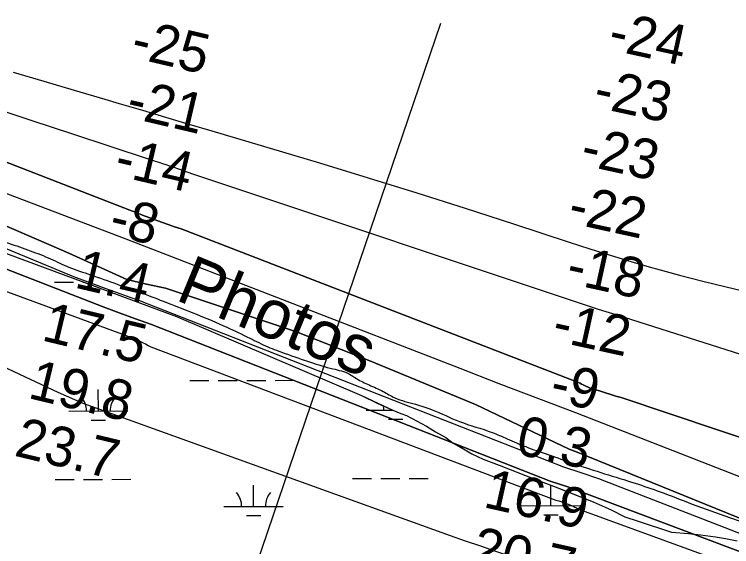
# Model space of a CAD drawing. Extents: x 3361039 to 3398939, y 576572 to 602007.
# Drawn here: x 3392837 to 3394047, y 583836 to 584734 of the extents above; entities that cross this region are included whole.
import ezdxf

# ---------------------------------------------------------------- set-up
doc = ezdxf.new("R2010")
doc.units = 0
for name, color, linetype in [('V-RIVR-EDGE', 7, 'Continuous'), ('V-RIVR-IDEN', 7, 'Continuous'), ('V-RIVR-RANG', 7, 'Continuous'), ('V-SITE-VEGE', 7, 'Continuous'), ('V-TOPO-DPTH', 7, 'Continuous'), ('V-TOPO-MINR', 7, 'Continuous'), ('V-TOPO-WATR', 7, 'Continuous'), ('V-WETL-SWMP', 7, 'Continuous')]:
    doc.layers.add(name, color=color, linetype=linetype)

msp = doc.modelspace()

# ---------------------------------------------------------------- linework, layer by layer
at = {"layer": 'V-RIVR-EDGE'}
msp.add_spline([(3387368.6, 585771), (3387389, 585767.6), (3387407.3, 585766.1), (3387418.2, 585761.7), (3387425.5, 585756.5), (3387441.6, 585752.8), (3387452.6, 585751.4), (3387462.1, 585753.9), (3387477.4, 585758.2), (3387482.9, 585759.3), (3387491.7, 585759.3), (3387502.3, 585758.2), (3387510.3, 585756.3), (3387521.6, 585753), (3387530.1, 585752.3), (3387538.5, 585752.2), (3387549.8, 585752.2), (3387558.9, 585755.5), (3387571.4, 585756.9), (3387583.4, 585757.3), (3387598.4, 585756.1), (3387629.8, 585749.5), (3387659.8, 585743.5), (3387703.3, 585736.8), (3387727.4, 585734.2), (3387739.1, 585733.5), (3387750.8, 585734.2), (3387753.7, 585731.6), (3387763.2, 585723.9), (3387774.5, 585720.6), (3387790.6, 585719.8), (3387800.1, 585721.6), (3387814, 585720.1), (3387824.6, 585720.1), (3387847.3, 585714.2), (3387884.2, 585709.4), (3387930.2, 585702.7), (3387980.6, 585701.1), (3388035.1, 585696.5), (3388076, 585694.6), (3388096.9, 585693.8), (3388120.3, 585690.5), (3388145.1, 585685.3), (3388171.8, 585682.3), (3388198.8, 585676.8), (3388222.6, 585669.4), (3388245.6, 585660.6), (3388260.9, 585655.4), (3388279.6, 585655.4), (3388291.3, 585658.3), (3388298.9, 585663.7), (3388299.3, 585666.3), (3388299, 585670.7), (3388290.6, 585674.4), (3388291.7, 585677.3), (3388293.9, 585678.4), (3388303, 585677.6), (3388318.7, 585676.5), (3388334.1, 585672.8), (3388354.1, 585663.6), (3388357.1, 585659.9), (3388363.3, 585658.1), (3388368.4, 585658.1), (3388371, 585661), (3388375.3, 585662.1), (3388379, 585661.3), (3388383, 585659.1), (3388383.7, 585654.4), (3388384.1, 585649.3), (3388389.9, 585647.4), (3388406, 585642.3), (3388468.9, 585637.7), (3388491.5, 585635.8), (3388534.6, 585628.4), (3388578.1, 585619.2), (3388610.6, 585613.6), (3388635.9, 585612.1), (3388727.9, 585599.4), (3388768.5, 585591.7), (3388822.6, 585580.9), (3388865, 585570.6), (3388906.6, 585562.8), (3388924.1, 585559.5), (3388938.8, 585562), (3388961.4, 585563.4), (3388974.2, 585560.1), (3389007.5, 585553.4), (3389018.8, 585554.5), (3389027.2, 585555.9), (3389037.1, 585555.9), (3389051.7, 585553.7), (3389061.2, 585553.3), (3389081.3, 585552.1), (3389098.1, 585551), (3389120.4, 585548.7), (3389143.4, 585546.5), (3389160.2, 585542.1), (3389200.8, 585534.7), (3389222.3, 585525.1), (3389247.2, 585519.2), (3389280.4, 585509.6), (3389307.5, 585497.8), (3389334.5, 585487.2), (3389349.5, 585483.1), (3389361.5, 585483.1), (3389382.7, 585479), (3389397, 585476.8), (3389416.7, 585468.7), (3389441.9, 585458.4), (3389464.9, 585451.4), (3389479.5, 585449.2), (3389506.2, 585446.2), (3389533.2, 585447.2), (3389558.5, 585444.2), (3389577.8, 585437.9), (3389603.4, 585431.3), (3389618.7, 585425.1), (3389639.2, 585415.1), (3389657.8, 585410.3), (3389693.2, 585404.8), (3389768.9, 585383), (3389806.5, 585373), (3389854.3, 585362.3), (3389881.7, 585358.6), (3389913.9, 585354.5), (3389953.7, 585349.3), (3390008.2, 585341.8), (3390037.8, 585336.3), (3390074.3, 585327.8), (3390128, 585312.7), (3390164.5, 585301.6), (3390200.7, 585289.8), (3390292.7, 585255.6), (3390327.1, 585241.3), (3390360.7, 585231.7), (3390404.5, 585221), (3390454.9, 585214.3), (3390483.1, 585210.5), (3390491.8, 585209.4), (3390494.4, 585207.2), (3390501.3, 585201), (3390507.9, 585200.6), (3390527.3, 585196.2), (3390545.9, 585195), (3390557.6, 585194.3), (3390574.4, 585189.8), (3390605.5, 585179.5), (3390698.6, 585148.2), (3390763.2, 585126.9), (3390811.1, 585111), (3390852.4, 585097.8), (3390900.9, 585081.6), (3390948.1, 585063.5), (3390993.7, 585048.4), (3391036.8, 585031.9), (3391070.8, 585020.1), (3391140.5, 584997.6), (3391201.5, 584974.1), (3391247.5, 584957.5), (3391310.7, 584933.6), (3391362.2, 584914.8), (3391400.6, 584900.1), (3391441.8, 584885.7), (3391505.4, 584861.1), (3391563.5, 584841.9), (3391658.8, 584807.3), (3391712.8, 584786), (3391758.8, 584767.3), (3391796.1, 584749.6), (3391880.4, 584718.3), (3391926.8, 584701.4), (3391969.2, 584685.2), (3392003.9, 584666.9), (3392040, 584650.3), (3392077.6, 584636), (3392135.7, 584613.2), (3392164.9, 584598.1), (3392196, 584583.8), (3392224.8, 584578.2), (3392263.5, 584567.9), (3392290.6, 584559.8), (3392322.7, 584546.5), (3392396.5, 584512.7), (3392439.9, 584496.2), (3392471.7, 584484.8), (3392502, 584473.3), (3392510.8, 584467.5), (3392535.2, 584458.3), (3392606.1, 584432.9), (3392632.4, 584421.5), (3392666.7, 584406.8), (3392715.6, 584386.9), (3392777.4, 584364.8), (3392827, 584348.3), (3392863.6, 584335.4), (3392897.9, 584321.8), (3392928.6, 584307.8), (3392965.4, 584294.9), (3393010, 584279.1), (3393054.6, 584263.2), (3393092.5, 584248.5), (3393195.2, 584206.6), (3393234.2, 584187.9), (3393264.5, 584173.5), (3393294.1, 584162.1), (3393336.8, 584147.4), (3393374.5, 584136.3), (3393402.2, 584127.5), (3393414.3, 584119.8), (3393435.4, 584109.1), (3393459.2, 584098.1), (3393478.9, 584087.5), (3393513.6, 584076.4), (3393541.7, 584067.2), (3393588.1, 584047.4), (3393643.2, 584028.9), (3393668.4, 584018.3), (3393699.8, 584005), (3393737.1, 583991.8), (3393781.7, 583976), (3393884.7, 583943.2), (3393927, 583928.8), (3393981.1, 583908.2), (3394043.9, 583885.4), (3394095.8, 583868.1), (3394154.9, 583847.1), (3394200.2, 583830.5), (3394247, 583816.2), (3394293, 583801.4), (3394349.6, 583781.2), (3394409.1, 583754.7), (3394451.8, 583730.5), (3394470.5, 583720.2), (3394481.8, 583715.4), (3394494.2, 583713.6), (3394502.6, 583708.1), (3394507.3, 583700.4), (3394511.3, 583697.8), (3394522.7, 583692.3), (3394557.3, 583675.8), (3394600.4, 583659.9), (3394658.1, 583638.9), (3394704.5, 583623.5), (3394760.4, 583607.6), (3394824, 583588.8), (3394867.8, 583570.8), (3394925.9, 583546.9), (3394972.2, 583528.9), (3394995.6, 583520), (3395064.7, 583504.2), (3395088.4, 583499.3), (3395120.2, 583491.6), (3395149.1, 583480.5), (3395173.2, 583476.8), (3395201.3, 583471.3), (3395236.4, 583459.9), (3395256.8, 583451.8), (3395280.9, 583445.5), (3395300.3, 583445.1), (3395316.7, 583440.7), (3395324.4, 583433.3), (3395335.3, 583426), (3395353.6, 583417.9), (3395398.9, 583403.9), (3395426.3, 583397.2), (3395442, 583391), (3395455.9, 583383.3), (3395476, 583377.8), (3395495.7, 583369.3), (3395511, 583368.2), (3395530.4, 583365.9), (3395550.5, 583361.8), (3395654.6, 583334.9), (3395704.7, 583322.4), (3395743.7, 583306.9), (3395765.3, 583295.5), (3395788.3, 583286.3), (3395816.4, 583278.9), (3395861.7, 583270.8), (3395916.2, 583261.5), (3395960.7, 583252.6), (3396008.6, 583242.6), (3396060.8, 583230.5), (3396093.4, 583222.3), (3396135.4, 583208.7), (3396170.1, 583199.8), (3396204.4, 583191.3), (3396254.8, 583177.3), (3396301.2, 583165.9), (3396364.4, 583152.9), (3396399.1, 583144.4), (3396426.9, 583138.5), (3396463.1, 583133), (3396489.8, 583132.9), (3396523.4, 583130.2), (3396607.8, 583114), (3396670.3, 583102.1), (3396708.3, 583095.4), (3396743, 583089.5), (3396775.1, 583083.9)], degree=3, dxfattribs=at)
at = {"layer": 'V-RIVR-RANG'}
msp.add_line((3393169.6, 583583.4), (3393556.8, 584719.2), dxfattribs=at)
at = {"layer": 'V-SITE-VEGE'}
for p, q in [((3392696.5, 584377.7), (3393110.5, 584224.5)), ((3393110.5, 584224.5), (3393422.5, 584091.4)), ((3393422.5, 584091.4), (3393450.5, 584078)), ((3393450.5, 584078), (3393475.6, 584066.4)), ((3393475.6, 584066.4), (3393489.2, 584061.1)), ((3393489.2, 584061.1), (3393498.7, 584057.7)), ((3393498.7, 584057.7), (3393515.7, 584048.8)), ((3393515.7, 584048.8), (3393532.5, 584039.8)), ((3393532.5, 584039.8), (3393547.4, 584030.2)), ((3393547.4, 584030.2), (3393565.3, 584020.2)), ((3393565.3, 584020.2), (3393577.2, 584011.1)), ((3393577.2, 584011.1), (3393609, 583992.8)), ((3393609, 583992.8), (3393627.8, 583983.8)), ((3393627.8, 583983.8), (3393655.2, 583973.6)), ((3393655.2, 583973.6), (3393715.3, 583949.9)), ((3393715.3, 583949.9), (3393746.6, 583938.2)), ((3393746.6, 583938.2), (3393813.9, 583911.9)), ((3393813.9, 583911.9), (3393844, 583898.3)), ((3393844, 583898.3), (3393867, 583886.8)), ((3393867, 583886.8), (3393889.8, 583879)), ((3393889.8, 583879), (3393945.8, 583860.5)), ((3393945.8, 583860.5), (3393974.4, 583858.5)), ((3393974.4, 583858.5), (3393995.1, 583856.4)), ((3393995.1, 583856.4), (3394020, 583852.8)), ((3394020, 583852.8), (3394037.2, 583850)), ((3394037.2, 583850), (3394056.8, 583846.3))]:
    msp.add_line(p, q, dxfattribs=at)
at = {"layer": 'V-TOPO-DPTH'}
for points in [[(3394697.5, 583807.4), (3393861, 584087.8), (3393852.2, 584090.4), (3393843.5, 584093.1), (3393834.8, 584095.7), (3393826.1, 584098.3), (3393816.3, 584101.3), (3393812.5, 584102.5), (3393808.8, 584103.9), (3393805.1, 584105.4), (3393801.5, 584107.1), (3393799.2, 584108.2), (3393796.8, 584109.4), (3393794.3, 584110.6), (3393791.9, 584111.8), (3393118, 584372.5), (3393107.1, 584376), (3393096.1, 584379.7), (3393085.3, 584383.5), (3393074.4, 584387.5), (3393063.7, 584391.6), (3393052.9, 584395.7), (3393042.2, 584399.9), (3393031.5, 584404.1), (3392383, 584655.6)], [(3392383, 584655.6), (3393031.5, 584404.1), (3393042.2, 584399.9), (3393052.9, 584395.7), (3393063.7, 584391.6), (3393074.4, 584387.5), (3393085.3, 584383.5), (3393096.1, 584379.7), (3393107.1, 584376), (3393118, 584372.5), (3393791.9, 584111.8), (3393794.3, 584110.6), (3393796.8, 584109.4), (3393799.2, 584108.2), (3393801.5, 584107.1), (3393805.1, 584105.4), (3393808.8, 584103.9), (3393812.5, 584102.5), (3393816.3, 584101.3), (3393826.1, 584098.3), (3393834.8, 584095.7), (3393843.5, 584093.1), (3393852.2, 584090.4), (3393861, 584087.8), (3394697.5, 583807.4)], [(3392834.9, 584637), (3392886.4, 584621.7), (3392937.8, 584606.5), (3392989.2, 584591.3), (3393013.8, 584584.1), (3393052.9, 584572.5), (3393092.1, 584560.9), (3393131.2, 584549.3), (3393170.3, 584537.7), (3393351.6, 584483.6), (3393433.7, 584458.7), (3393515.8, 584433.4), (3393597.6, 584407.3), (3393679.2, 584380.9), (3393773.4, 584349.9), (3393807.9, 584338.8), (3393842.6, 584327.9), (3393877.3, 584317.5), (3393912.2, 584307.3), (3393920.5, 584305), (3393959.6, 584294.2), (3393998.9, 584283.9), (3394038.4, 584274.4), (3394078, 584265.3)], [(3392834.9, 584637), (3392886.4, 584621.7), (3392937.8, 584606.5), (3392989.2, 584591.3), (3393013.8, 584584.1), (3393052.9, 584572.5), (3393092.1, 584560.9), (3393131.2, 584549.3), (3393170.3, 584537.7), (3393351.6, 584483.6), (3393433.7, 584458.7), (3393515.8, 584433.4), (3393597.6, 584407.3), (3393679.2, 584380.9), (3393773.4, 584349.9), (3393807.9, 584338.8), (3393842.6, 584327.9), (3393877.3, 584317.5), (3393912.2, 584307.3), (3393920.5, 584305), (3393959.6, 584294.2), (3393998.9, 584283.9), (3394038.4, 584274.4), (3394078, 584265.3)], [(3395292.5, 583438.3), (3395001.1, 583522.6), (3394918.6, 583546.3), (3394836.2, 583569.8), (3394753.6, 583593.2), (3394671.1, 583616.4), (3394566.6, 583645.6), (3394536.2, 583654.1), (3394505.9, 583662.8), (3394475.7, 583671.6), (3393772.5, 583936.8), (3393756.9, 583941.8), (3393741.3, 583946.8), (3393068.1, 584211), (3393041, 584220.8), (3393013.8, 584230.7), (3392986.7, 584240.6), (3392333.6, 584495.2)], [(3395337.7, 583469.1), (3395000.8, 583574.7), (3394620.5, 583676.1), (3394541.3, 583694.2), (3394525.2, 583696.7), (3394503.9, 583703.6), (3394452.9, 583725), (3393786.9, 583995.7), (3393773.3, 584000.9), (3393615.1, 584076.2), (3393436.5, 584149.8), (3393313.1, 584198.7), (3393092, 584272.4), (3393059.6, 584279.3), (3393026.4, 584287.1), (3392928.6, 584331.6), (3392676, 584440.3)], [(3392676, 584440.3), (3392928.6, 584331.6), (3393026.4, 584287.1), (3393059.6, 584279.3), (3393092, 584272.4), (3393313.1, 584198.7), (3393436.5, 584149.8), (3393615.1, 584076.2), (3393773.3, 584000.9), (3393786.9, 583995.7), (3394452.9, 583725), (3394503.9, 583703.6), (3394525.2, 583696.7), (3394541.3, 583694.2), (3394620.5, 583676.1), (3395000.8, 583574.7), (3395337.7, 583469.1)]]:
    msp.add_lwpolyline(points, dxfattribs=at)
at = {"layer": 'V-TOPO-MINR'}
for points in [[(3392383, 584655.6), (3393031.5, 584404.1), (3393042.2, 584399.9), (3393052.9, 584395.7), (3393063.7, 584391.6), (3393074.4, 584387.5), (3393085.3, 584383.5), (3393096.1, 584379.7), (3393107.1, 584376), (3393118, 584372.5), (3393791.9, 584111.8), (3393794.3, 584110.6), (3393796.8, 584109.4), (3393799.2, 584108.2), (3393801.5, 584107.1), (3393805.1, 584105.4), (3393808.8, 584103.9), (3393812.5, 584102.5), (3393816.3, 584101.3), (3393826.1, 584098.3), (3393834.8, 584095.7), (3393843.5, 584093.1), (3393852.2, 584090.4), (3393861, 584087.8), (3394697.5, 583807.4)], [(3392834.9, 584637), (3392886.4, 584621.7), (3392937.8, 584606.5), (3392989.2, 584591.3), (3393013.8, 584584.1), (3393052.9, 584572.5), (3393092.1, 584560.9), (3393131.2, 584549.3), (3393170.3, 584537.7), (3393351.6, 584483.6), (3393433.7, 584458.7), (3393515.8, 584433.4), (3393597.6, 584407.3), (3393679.2, 584380.9), (3393773.4, 584349.9), (3393807.9, 584338.8), (3393842.6, 584327.9), (3393877.3, 584317.5), (3393912.2, 584307.3), (3393920.5, 584305), (3393959.6, 584294.2), (3393998.9, 584283.9), (3394038.4, 584274.4), (3394078, 584265.3)], [(3392413.4, 584588.1), (3393024.8, 584355.3), (3393588.5, 584137.2), (3393654.6, 584111.3), (3393783.7, 584062.7), (3394503, 583781.8), (3394527.2, 583771.3), (3394551.6, 583761.1), (3394576, 583751.1), (3394629.6, 583729.8), (3394681.1, 583709.8), (3394732.9, 583690.6), (3394785, 583672.4), (3394837.4, 583655), (3395352.5, 583489)], [(3392795, 584578.6), (3392864.8, 584555.5), (3392934.7, 584532.5), (3393062.5, 584490.6), (3393068.5, 584488.7), (3393074.5, 584486.7), (3393080.5, 584484.8), (3393086.5, 584482.8), (3393092.5, 584480.8), (3393098.5, 584478.8), (3393104.5, 584476.8), (3393110.5, 584474.8), (3393114, 584473.6), (3393121.7, 584470.9), (3393129.5, 584468.2), (3393137.2, 584465.5), (3393822.4, 584236.9), (3393853.7, 584227.5), (3394308.1, 584083.1)], [(3392333.6, 584495.2), (3392986.7, 584240.6), (3393013.8, 584230.7), (3393041, 584220.8), (3393068.1, 584211), (3393741.3, 583946.8), (3393756.9, 583941.8), (3393772.5, 583936.8), (3394475.7, 583671.6), (3394505.9, 583662.8), (3394536.2, 583654.1), (3394566.6, 583645.6), (3394671.1, 583616.4), (3394753.6, 583593.2), (3394836.2, 583569.8), (3394918.6, 583546.3), (3395001.1, 583522.6), (3395292.5, 583438.3)], [(3392256.5, 584475.3), (3393034.3, 584188.9), (3393039.2, 584187.1), (3393043.9, 584185.1), (3393048.6, 584182.9), (3393053.2, 584180.6), (3393057.8, 584178.2), (3393062.3, 584175.8), (3393066.9, 584173.3), (3393746.3, 583916.2), (3393750.9, 583914.7), (3393753.2, 583914), (3393755.6, 583913.3), (3393768.7, 583909.1), (3393771.6, 583908.1), (3393774.4, 583907), (3393777.2, 583905.7), (3393780, 583904.3), (3393782.7, 583902.9), (3393785.4, 583901.5), (3393788.1, 583900.1), (3394463.4, 583653.6)], [(3392503.1, 584471.7), (3392936.5, 584291.9), (3392995.9, 584270.1), (3393008.4, 584265.6), (3393021, 584261), (3393033.6, 584256.5), (3393046.1, 584251.9), (3393763.4, 583970.9), (3393793.1, 583961.2), (3393822.8, 583951.3), (3394510.2, 583684.8), (3394529.7, 583679.2), (3394549.1, 583673.6), (3394843.9, 583589.4), (3394929.4, 583564.9), (3395014.9, 583540.5), (3395100.4, 583516), (3395185.8, 583491.4)], [(3392293, 584386.4), (3392910, 584097.1), (3392952.5, 584078.2), (3393572.4, 583855.2), (3393597.9, 583846.3), (3393623.5, 583837.4), (3393649.1, 583828.7), (3393674.8, 583820), (3393716.8, 583805.9), (3393721.5, 583804.4), (3393726.1, 583802.9), (3394442.8, 583590.5), (3394465.7, 583582.8), (3394488.5, 583574.7), (3394511.2, 583566.1), (3395350.3, 583253.7)]]:
    msp.add_lwpolyline(points, dxfattribs=at)
at = {"layer": 'V-TOPO-WATR'}
msp.add_lwpolyline([(3395337.7, 583469.1), (3395000.8, 583574.7), (3394620.5, 583676.1), (3394541.3, 583694.2), (3394525.2, 583696.7), (3394503.9, 583703.6), (3394452.9, 583725), (3393786.9, 583995.7), (3393773.3, 584000.9), (3393615.1, 584076.2), (3393436.5, 584149.8), (3393313.1, 584198.7), (3393092, 584272.4), (3393059.6, 584279.3), (3393026.4, 584287.1), (3392928.6, 584331.6), (3392676, 584440.3)], dxfattribs=at)
at = {"layer": 'V-WETL-SWMP'}
for p, q in [((3392696.5, 584377.7), (3393110.5, 584224.5)), ((3392904.5, 584282.2), (3392936.5, 584282.3)), ((3392952.5, 584282.4), (3392954.1, 584282.4)), ((3393110.5, 584224.5), (3393422.5, 584091.4)), ((3393133, 584116.4), (3393165, 584116.5)), ((3393181, 584116.5), (3393213, 584116.6)), ((3393229, 584116.6), (3393261, 584116.7)), ((3393277, 584116.8), (3393309, 584116.9)), ((3392978.5, 584065.2), (3392978.4, 584101.2)), ((3393422.5, 584091.4), (3393450.5, 584078.1)), ((3393450.5, 584078.1), (3393475.6, 584066.4)), ((3392928.5, 584065.1), (3393028.5, 584065.3)), ((3393430.4, 584066.5), (3393475.1, 584066.6)), ((3393475.6, 584066.4), (3393489.2, 584061.1)), ((3393489.2, 584061.1), (3393498.7, 584057.7)), ((3392966.6, 584049.7), (3392990.6, 584049.8)), ((3393468.5, 584051.1), (3393492.5, 584051.2)), ((3393498.7, 584057.7), (3393515.7, 584048.8)), ((3393515.7, 584048.8), (3393532.5, 584039.8)), ((3393532.5, 584039.8), (3393547.4, 584030.2)), ((3393547.4, 584030.2), (3393565.3, 584020.3)), ((3393565.3, 584020.3), (3393577.2, 584011.1)), ((3393577.2, 584011.1), (3393591.8, 584002.7)), ((3393591.8, 584002.7), (3393609, 583992.8)), ((3393609, 583992.8), (3393627.8, 583983.8)), ((3393627.8, 583983.8), (3393655.2, 583973.6)), ((3393655.2, 583973.6), (3393715.3, 583949.9)), ((3393407.3, 583951), (3393439.3, 583951)), ((3393455.3, 583951.1), (3393487.3, 583951.2)), ((3393503.3, 583951.2), (3393535.3, 583951.3)), ((3392905.4, 583949.6), (3392937.4, 583949.7)), ((3392953.4, 583949.7), (3392985.4, 583949.8)), ((3393001.4, 583949.8), (3393033.4, 583949.9)), ((3393240.4, 583904.1), (3393240.3, 583940.1)), ((3393715.3, 583949.9), (3393746.6, 583938.2)), ((3393742.3, 583905.5), (3393742.2, 583939.8)), ((3393746.6, 583938.2), (3393777, 583926.3)), ((3393777, 583926.3), (3393813.9, 583911.9)), ((3393190.4, 583903.9), (3393290.4, 583904.2)), ((3393692.3, 583905.3), (3393792.3, 583905.6)), ((3393813.9, 583911.9), (3393844, 583898.3)), ((3393730.4, 583890), (3393754.4, 583890.1)), ((3393844, 583898.3), (3393867, 583886.8)), ((3393228.5, 583888.6), (3393252.5, 583888.7)), ((3393867, 583886.8), (3393889.8, 583879)), ((3393889.8, 583879), (3393945.8, 583860.5)), ((3393945.8, 583860.5), (3393974.4, 583858.5)), ((3393974.4, 583858.5), (3393995.1, 583856.4)), ((3393995.1, 583856.4), (3394020, 583852.8)), ((3394020, 583852.8), (3394037.2, 583850)), ((3394037.2, 583850), (3394056.8, 583846.3))]:
    msp.add_line(p, q, dxfattribs=at)
for centre, start, end in [((3392923.3, 584065.5), 359.3865, 40.9302), ((3393033.8, 584065.8), 139.3865, 180.9301), ((3393425.2, 584066.9), 359.3865, 11.1827), ((3393185.2, 583904.4), 359.3865, 40.9302), ((3393295.7, 583904.7), 139.3865, 180.9301), ((3393687.1, 583905.8), 359.3865, 40.9302), ((3393797.6, 583906.1), 139.9229, 180.9301)]:
    msp.add_arc(centre, 35.2, start, end, dxfattribs=at)

# ---------------------------------------------------------------- texts
at = {"layer": 'V-RIVR-IDEN'}
msp.add_text(' Photos', height=83, rotation=337.5669, dxfattribs=at).set_placement((3393078, 584265.1))
at = {"layer": 'V-RIVR-RANG'}
for s, rotation, p in [('-24', 347.6429, (3393836.5, 584675.7)), ('-25', 346.8099, (3393030.8, 584662.5)), ('-23', 347.6429, (3393811.5, 584578.8)), ('-21', 346.8099, (3393022.9, 584561.7)), ('-23', 347.6429, (3393789.8, 584481.2)), ('-14', 346.8099, (3393002.9, 584463.6)), ('-22', 347.6429, (3393768.7, 584383.4)), ('-8', 346.8099, (3392994, 584363)), ('1.4', 346.8099, (3392936.3, 584273.8)), ('-18', 347.6429, (3393765.6, 584281.7)), ('17.5', 346.5283, (3392880.8, 584184.7)), ('-12', 347.6429, (3393741.9, 584184.6)), ('19.8', 346.5283, (3392857.8, 584087.4)), ('-9', 347.6429, (3393738.1, 584083)), ('23.7', 346.5283, (3392834.7, 583990.1)), ('0.3', 347.6429, (3393680.9, 583993.2)), ('16.9', 347.3583, (3393626.5, 583903.3)), ('20.7', 347.3583, (3393605.1, 583805.7))]:
    msp.add_text(s, height=67, rotation=rotation, dxfattribs=at).set_placement(p)

doc.saveas('drawing.dxf')
